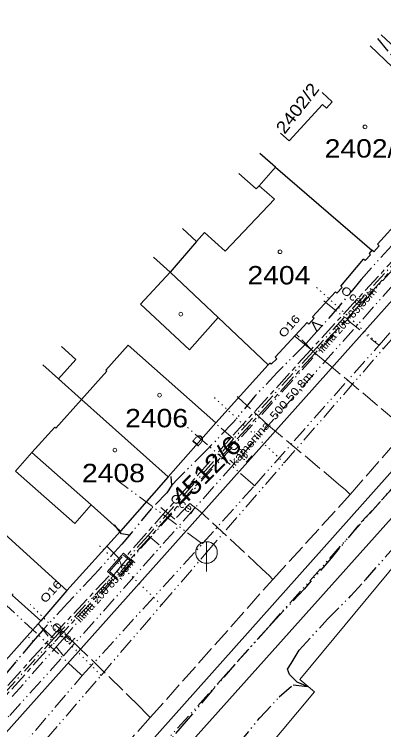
# Model space of a CAD drawing. Extents: x -683947 to -683762, y -1065756 to -1065543.
# Drawn here: x -683844 to -683809.8, y -1065615.3 to -1065549.1 of the extents above; entities that cross this region are included whole.
import ezdxf
from ezdxf.enums import TextEntityAlignment as Align

# ---------------------------------------------------------------- set-up
doc = ezdxf.new("R2010")
doc.units = 0
doc.header["$LTSCALE"] = 0.3
for name, pattern in [('DASH_DOUBLE_DOT', [9.2, 5, -1.2, 0.3, -1.2, 0.3, -1.2]), ('DOTTED', [1.5, 0.3, -1.2]), ('LONG_DASH_SHORT_DASH', [9.9, 6, -1.2, 1.5, -1.2]), ('LONG_DASHED', [7.5, 6, -1.5])]:
    doc.linetypes.add(name, pattern=pattern)
for name, color, linetype, lineweight in [('1', 7, 'Continuous', 25), ('10', 7, 'Continuous', 13), ('26', 7, 'LONG_DASH_SHORT_DASH', 13), ('30', 7, 'LONG_DASHED', 13), ('31', 7, 'DASH_DOUBLE_DOT', 13), ('35', 7, 'LONG_DASHED', 13), ('36', 7, 'DASH_DOUBLE_DOT', 25), ('4', 7, 'Continuous', 13), ('41', 7, 'DASH_DOUBLE_DOT', 13), ('46', 7, 'DASH_DOUBLE_DOT', 13), ('5', 7, 'Continuous', 13), ('50', 7, 'LONG_DASHED', 13), ('51', 7, 'DOTTED', 13)]:
    doc.layers.add(name, color=color, linetype=linetype, lineweight=lineweight)
for name, color, linetype in [('15', 7, 'Continuous'), ('16', 7, 'Continuous'), ('19', 7, 'Continuous'), ('2', 7, 'Continuous')]:
    doc.layers.add(name, color=color, linetype=linetype)

msp = doc.modelspace()

# ---------------------------------------------------------------- linework, layer by layer
at = {"layer": '1'}
for p, q in [((-683811.072, -1065552.024), (-683809.01, -1065554)), ((-683815.487, -1065556.329), (-683814.57, -1065557.2)), ((-683814.57, -1065557.2), (-683815.09, -1065557.77)), ((-683815.46, -1065557.44), (-683818.54, -1065560.8)), ((-683815.09, -1065557.77), (-683815.46, -1065557.44)), ((-683818.54, -1065560.8), (-683819.342, -1065560.088)), ((-683819.83, -1065563.25), (-683821.28, -1065561.977)), ((-683819.83, -1065563.25), (-683810.9, -1065570.93)), ((-683799.39, -1065564.75), (-683850.61, -1065622.17)), ((-683828.408, -1065568.928), (-683827.11, -1065570.14)), ((-683827.11, -1065570.14), (-683829.57, -1065572.98)), ((-683810.9, -1065570.93), (-683811.16, -1065571.23)), ((-683831.113, -1065571.565), (-683829.57, -1065572.98)), ((-683813.78, -1065574.26), (-683811.67, -1065571.76)), ((-683811.53, -1065571.89), (-683811.67, -1065571.76)), ((-683811.02, -1065571.36), (-683811.53, -1065571.89)), ((-683811.16, -1065571.23), (-683811.02, -1065571.36)), ((-683829.57, -1065572.98), (-683825.13, -1065577.17)), ((-683825.13, -1065577.17), (-683820.49, -1065581.56)), ((-683844.35, -1065631.04), (-683799.69, -1065580.85)), ((-683841.345, -1065581.543), (-683839.89, -1065582.84)), ((-683839.89, -1065582.84), (-683837.75, -1065584.76)), ((-683837.75, -1065584.76), (-683829.74, -1065591.91)), ((-683839.12, -1065602.44), (-683851.364, -1065591.312)), ((-683809.1, -1065595.75), (-683842.21, -1065632.76)), ((-683834.14, -1065596.93), (-683839.12, -1065602.44)), ((-683839.12, -1065602.44), (-683841.53, -1065605.24)), ((-683841.53, -1065605.24), (-683848.31, -1065612.84))]:
    msp.add_line(p, q, dxfattribs=at)
for points in [[(-683808.27, -1065568.02), (-683810.39, -1065570.39), (-683810.24, -1065570.54), (-683810.72, -1065571.09), (-683810.9, -1065570.93)], [(-683813.78, -1065574.26), (-683813.64, -1065574.38), (-683814.14, -1065574.92)], [(-683814.14, -1065574.92), (-683814.27, -1065574.8), (-683816.4, -1065577.11), (-683816.25, -1065577.24), (-683816.75, -1065577.77), (-683816.89, -1065577.64), (-683819.85, -1065580.85)], [(-683819.85, -1065580.85), (-683819.7, -1065580.98), (-683820.21, -1065581.49), (-683820.34, -1065581.38), (-683820.49, -1065581.56)], [(-683820.49, -1065581.56), (-683825.32, -1065586.92), (-683829.74, -1065591.91), (-683834.14, -1065596.93)]]:
    msp.add_lwpolyline(points, dxfattribs=at)
at = {"layer": '10'}
msp.add_line((-683826.197, -1065597.916), (-683826.197, -1065600.664), dxfattribs=at)
msp.add_circle((-683826.197, -1065598.918), 1, dxfattribs=at)
at = {"layer": '26'}
for points in [[(-683802.34, -1065565.06), (-683804.28, -1065566.78), (-683816.53, -1065580.13), (-683823.89, -1065588.24), (-683833.6, -1065599.23)], [(-683802.02, -1065565.39), (-683803.92, -1065567.14), (-683816.16, -1065580.47), (-683823.51, -1065588.58), (-683833.25, -1065599.54)], [(-683861.16, -1065628.68), (-683852.54, -1065620.04), (-683840.5, -1065606.72), (-683835.07, -1065600.93)], [(-683860.72, -1065629.09), (-683852.18, -1065620.38), (-683840.14, -1065607.06), (-683834.72, -1065601.23)]]:
    msp.add_lwpolyline(points, dxfattribs=at)
for points in [[(-683835.35, -1065600.68), (-683834.29, -1065599.47), (-683833.88, -1065598.99), (-683833.6, -1065599.23), (-683833.25, -1065599.54), (-683832.97, -1065599.78), (-683834.44, -1065601.47), (-683834.72, -1065601.23), (-683835.07, -1065600.93)], [(-683835.18, -1065600.67), (-683833.87, -1065599.16), (-683833.14, -1065599.79), (-683834.45, -1065601.3)]]:
    msp.add_lwpolyline(points, close=True, dxfattribs=at)
at = {"layer": '30', "linetype": 'DASH_DOUBLE_DOT'}
for p, q in [((-683823.7, -1065588.41), (-683825.26, -1065587.05)), ((-683840.32, -1065606.89), (-683841.75, -1065605.57))]:
    msp.add_line(p, q, dxfattribs=at)
at = {"layer": '31'}
for p, q in [((-683823.7, -1065588.41), (-683831.6, -1065597.35)), ((-683852.36, -1065620.21), (-683840.32, -1065606.89))]:
    msp.add_line(p, q, dxfattribs=at)
for points in [[(-683844.16, -1065612.25), (-683839.52, -1065607), (-683832.27, -1065598.52), (-683799.27, -1065561.98), (-683793.42, -1065555.08), (-683787.795, -1065549.096)], [(-683841.77, -1065605.48), (-683839.42, -1065608.5), (-683799.62, -1065563.63)], [(-683801.38, -1065564.44), (-683804.1, -1065566.96), (-683816.34, -1065580.3), (-683823.7, -1065588.41)], [(-683816.34, -1065580.3), (-683817.76, -1065578.85), (-683817.93, -1065578.7)], [(-683830.59, -1065598.2), (-683831.6, -1065597.35), (-683834.07, -1065600.11)], [(-683835.38, -1065598.38), (-683834.29, -1065599.47), (-683834.07, -1065600.11)], [(-683840.32, -1065606.89), (-683834.87, -1065601.11), (-683834.07, -1065600.11)], [(-683851.65, -1065622.08), (-683844.4, -1065614), (-683839.42, -1065608.5)]]:
    msp.add_lwpolyline(points, dxfattribs=at)
at = {"layer": '35'}
msp.add_lwpolyline([(-683896.24, -1065687.55), (-683894.71, -1065685.72), (-683893.48, -1065684.13), (-683891.61, -1065681.955), (-683887.89, -1065677.63), (-683886.16, -1065675.53), (-683853.44, -1065639.1), (-683848.45, -1065633.59), (-683843.114, -1065627.22), (-683843.08, -1065627.18), (-683831.4, -1065614.21), (-683820.06, -1065601.41), (-683812.91, -1065593.55), (-683807.75, -1065587.62), (-683793.84, -1065572.21), (-683791.969, -1065570.179), (-683790.708, -1065568.809), (-683790.074, -1065568.129)], dxfattribs=at)
at = {"layer": '36'}
for p, q in [((-683816.44, -1065577.61), (-683816, -1065578.45)), ((-683815.51, -1065577.95), (-683816.44, -1065577.61)), ((-683816, -1065578.45), (-683815.51, -1065577.95))]:
    msp.add_line(p, q, dxfattribs=at)
at = {"layer": '36', "linetype": 'DOTTED', "lineweight": 13}
msp.add_line((-683842.215, -1065607.115), (-683842.69, -1065606.74), dxfattribs=at)
at = {"layer": '36'}
for points in [[(-683810.38, -1065551.349), (-683808.92, -1065553.09), (-683807.88, -1065553.96), (-683808.28, -1065554.7)], [(-683800.49, -1065560.55), (-683800.89, -1065561.47), (-683802.33, -1065563.11), (-683804.19, -1065565.23), (-683806.4, -1065567.64), (-683809.07, -1065570.49), (-683811.9, -1065573.65), (-683813.94, -1065576.12), (-683815.51, -1065577.95)], [(-683780.391, -1065561.807), (-683782.7, -1065564.42), (-683783.44, -1065565.28), (-683785.65, -1065567.7), (-683788.09, -1065570.32), (-683790.52, -1065572.55), (-683793.62, -1065575.94), (-683795.75, -1065578.2), (-683797.85, -1065580.61), (-683800.07, -1065583.11), (-683802.78, -1065586.29), (-683805.93, -1065589.86), (-683808.99, -1065592.97), (-683812.14, -1065596.4), (-683814.68, -1065599.44), (-683817.17, -1065602.3), (-683820.49, -1065605.87), (-683823.62, -1065609.31), (-683825.7, -1065611.73), (-683828.07, -1065614.55), (-683831.17, -1065618.13)], [(-683816, -1065578.45), (-683817.14, -1065579.74), (-683819.66, -1065582.26), (-683821.73, -1065584.46), (-683823.76, -1065586.92), (-683826.23, -1065589.48), (-683828.84, -1065592.09), (-683829.39, -1065592.7), (-683829.46, -1065591.89)], [(-683829.39, -1065592.7), (-683829.87, -1065593.39), (-683831.28, -1065594.84), (-683833.33, -1065597.33)], [(-683833.33, -1065597.33), (-683834.06, -1065597.2), (-683834.7, -1065596.36)], [(-683833.33, -1065597.33), (-683834.03, -1065598.15), (-683836.56, -1065600.97), (-683839.02, -1065603.58), (-683841.41, -1065606.16), (-683842.215, -1065607.115)], [(-683816.844, -1065611.315), (-683817.806, -1065610.911), (-683818.52, -1065610.227), (-683818.714, -1065609.734), (-683818.377, -1065609.192), (-683817.615, -1065607.976), (-683815.022, -1065605.096), (-683812.85, -1065602.939), (-683811.5, -1065601.448), (-683808.88, -1065598.46), (-683808.67, -1065598.185)], [(-683842.215, -1065607.115), (-683843.83, -1065609.03), (-683846.24, -1065611.96), (-683847.58, -1065613.3), (-683848.12, -1065613.6), (-683848.69, -1065613.45)], [(-683827.805, -1065638.885), (-683828.78, -1065637.97), (-683830.92, -1065636.23), (-683833.53, -1065634.06), (-683835.29, -1065632.31), (-683835.5, -1065631.78), (-683835.5, -1065631.33), (-683835.12, -1065630.55), (-683834.34, -1065629.49), (-683833.84, -1065629), (-683831.94, -1065626.56), (-683828.817, -1065623.147), (-683825.805, -1065619.899), (-683823.226, -1065616.647), (-683821.28, -1065614.232), (-683819.465, -1065612.274), (-683818.198, -1065611.186), (-683816.844, -1065611.315)]]:
    msp.add_lwpolyline(points, dxfattribs=at)
at = {"layer": '36', "lineweight": 13}
msp.add_lwpolyline([(-683853.405, -1065628.437), (-683847.424, -1065621.75), (-683837.692, -1065610.319), (-683826.563, -1065598.101), (-683821.765, -1065592.734), (-683810.241, -1065579.722), (-683798.152, -1065565.762), (-683797.335, -1065564.872), (-683796.84, -1065564.29)], dxfattribs=at)
at = {"layer": '4'}
for p, q in [((-683802.48, -1065558.07), (-683810.031, -1065551.009)), ((-683823.198, -1065563.848), (-683821.59, -1065565.26)), ((-683821.33, -1065564.96), (-683819.9, -1065566.21)), ((-683827.76, -1065580.16), (-683825.13, -1065577.17)), ((-683835.51, -1065582.03), (-683833.45, -1065579.72)), ((-683825.32, -1065586.92), (-683833.45, -1065579.72)), ((-683839.606, -1065579.847), (-683838.29, -1065581.04)), ((-683839.89, -1065582.84), (-683838.29, -1065581.04)), ((-683837.75, -1065584.76), (-683835.4, -1065582.13)), ((-683835.4, -1065582.13), (-683835.51, -1065582.03)), ((-683843.87, -1065591.38), (-683842.34, -1065589.65)), ((-683838.38, -1065596.25), (-683843.87, -1065591.38)), ((-683836.85, -1065594.52), (-683838.38, -1065596.25)), ((-683834.14, -1065596.93), (-683836.85, -1065594.52)), ((-683817.57, -1065610.69), (-683806.98, -1065597.89)), ((-683816.21, -1065611.83), (-683817.57, -1065610.69))]:
    msp.add_line(p, q, dxfattribs=at)
for points in [[(-683819.83, -1065563.25), (-683821.33, -1065564.96), (-683821.59, -1065565.26)], [(-683819.9, -1065566.21), (-683824.46, -1065571.01), (-683826.38, -1065569.3), (-683827.11, -1065570.14)], [(-683829.57, -1065572.98), (-683832.29, -1065575.92), (-683827.76, -1065580.16)], [(-683840.23, -1065587.31), (-683840.12, -1065587.41), (-683837.75, -1065584.76)], [(-683836.85, -1065594.52), (-683842.34, -1065589.65), (-683840.23, -1065587.31)], [(-683841.53, -1065605.24), (-683844.18, -1065602.88), (-683844.07, -1065602.76)], [(-683834.89, -1065631.34), (-683831.13, -1065626.86), (-683829.74, -1065628.03), (-683816.21, -1065611.83)]]:
    msp.add_lwpolyline(points, dxfattribs=at)
at = {"layer": '41', "lineweight": 25}
msp.add_lwpolyline([(-683907.26, -1065705.67), (-683893.37, -1065687.98), (-683887.71, -1065681.96), (-683876.81, -1065669.67), (-683869.01, -1065660.17), (-683861.43, -1065651.54), (-683852.89, -1065642.04), (-683845.02, -1065633.03), (-683836.31, -1065623.45), (-683820.34, -1065605.7), (-683789.54, -1065571.05), (-683781.76, -1065562.31), (-683777.124, -1065557.504)], dxfattribs=at)
at = {"layer": '46'}
for points in [[(-683826.197, -1065598.918), (-683819.004, -1065590.616), (-683809.84, -1065580.04), (-683792.885, -1065560.567)], [(-683852.585, -1065629.704), (-683846.423, -1065622.515), (-683835.949, -1065610.295), (-683830.355, -1065603.769), (-683826.197, -1065598.918)]]:
    msp.add_lwpolyline(points, dxfattribs=at)
at = {"layer": '5'}
for centre in [(-683811.537, -1065559.519), (-683819.397, -1065571.079), (-683828.577, -1065576.859), (-683830.537, -1065584.359), (-683834.667, -1065589.439)]:
    msp.add_circle(centre, 0.175, dxfattribs=at)
at = {"layer": '50'}
for points in [[(-683807.75, -1065587.62), (-683808.08, -1065587.23), (-683808.653, -1065586.748), (-683814.89, -1065581.51), (-683818.084, -1065578.857)], [(-683812.91, -1065593.55), (-683813.33, -1065593.12), (-683813.976, -1065592.581), (-683820.47, -1065587.16), (-683823.269, -1065584.579), (-683823.374, -1065584.483)], [(-683820.06, -1065601.41), (-683820.39, -1065601.06), (-683821.04, -1065600.455), (-683826.77, -1065595.12), (-683827.75, -1065594.37), (-683829.12, -1065595.83), (-683830.43, -1065594.76)], [(-683831.4, -1065614.21), (-683831.83, -1065613.75), (-683832.343, -1065613.247), (-683838, -1065607.7), (-683840.21, -1065605.57)]]:
    msp.add_lwpolyline(points, dxfattribs=at)
at = {"layer": '51'}
for p, q in [((-683809.84, -1065580.04), (-683816.061, -1065574.329)), ((-683819.004, -1065590.616), (-683825.503, -1065584.544)), ((-683830.355, -1065603.769), (-683836.147, -1065598.228)), ((-683835.949, -1065610.295), (-683842.499, -1065603.723))]:
    msp.add_line(p, q, dxfattribs=at)
at = {"layer": '51', "linetype": 'DASH_DOUBLE_DOT'}
for points in [[(-683815.353, -1065575.631), (-683810.42, -1065579.59), (-683810.241, -1065579.722)], [(-683821.765, -1065592.734), (-683821.92, -1065592.59), (-683828.404, -1065586.96)], [(-683826.563, -1065598.101), (-683826.74, -1065597.98), (-683834.27, -1065592.391)], [(-683837.692, -1065610.319), (-683837.85, -1065610.18), (-683845.274, -1065603.286)]]:
    msp.add_lwpolyline(points, dxfattribs=at)

# ---------------------------------------------------------------- texts
at = {"layer": '15'}
for s, width, p in [('kamenina  500 50,8m', 1.15, (-683823.541, -1065590.965)), ('D', 1.6, (-683827.053, -1065589.217))]:
    msp.add_text(s, height=0.75, rotation=49.09, dxfattribs=dict(at, width=width)).set_placement(p)
at = {"layer": '16'}
for rotation, p in [(48.47, (-683815.474, -1065580.503)), (47.67, (-683837.86, -1065605.455))]:
    msp.add_text('litina 200 85,53m', height=0.75, rotation=rotation, dxfattribs=at).set_placement(p)
at = {"layer": '16', "width": 1.25}
for rotation, p in [(48.47, (-683819.047, -1065579.107)), (47.67, (-683841.105, -1065603.67))]:
    msp.add_text('O16', height=0.75, rotation=rotation, dxfattribs=at).set_placement(p)
at = {"layer": '19', "width": 1.2}
for rotation, p in [(323.64, (-683813.847, -1065574.797)), (318.49, (-683824.277, -1065589.009)), (326.26, (-683829.622, -1065594.051)), (317.98, (-683840.627, -1065605.856))]:
    msp.add_text('Ocel ', height=0.75, rotation=rotation, dxfattribs=at).set_placement(p)
at = {"layer": '2', "width": 1.15}
msp.add_text('2402/2', height=1.14, rotation=52.252, dxfattribs=at).set_placement((-683817.332, -1065558.143), align=Align.CENTER)
msp.add_text('2402/1', height=1.7, dxfattribs=at).set_placement((-683811.27, -1065562.36), align=Align.CENTER)
for s, p in [('2404', (-683822.41, -1065574.1)), ('2406', (-683833.72, -1065587.33)), ('2408', (-683837.71, -1065592.41))]:
    msp.add_text(s, height=1.7, dxfattribs=at).set_placement(p)
msp.add_text('4512/6', height=1.7, rotation=45.09, dxfattribs=at).set_placement((-683828.45, -1065594.81))

doc.saveas('drawing.dxf')
